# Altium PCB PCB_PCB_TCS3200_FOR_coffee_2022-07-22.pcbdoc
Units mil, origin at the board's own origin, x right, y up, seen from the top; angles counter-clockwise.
Board outline 2180 x 1812.92 mil, 2 copper layers (Top Layer, Bottom Layer); 51 components, 41 nets, 59 pads, 17 vias.
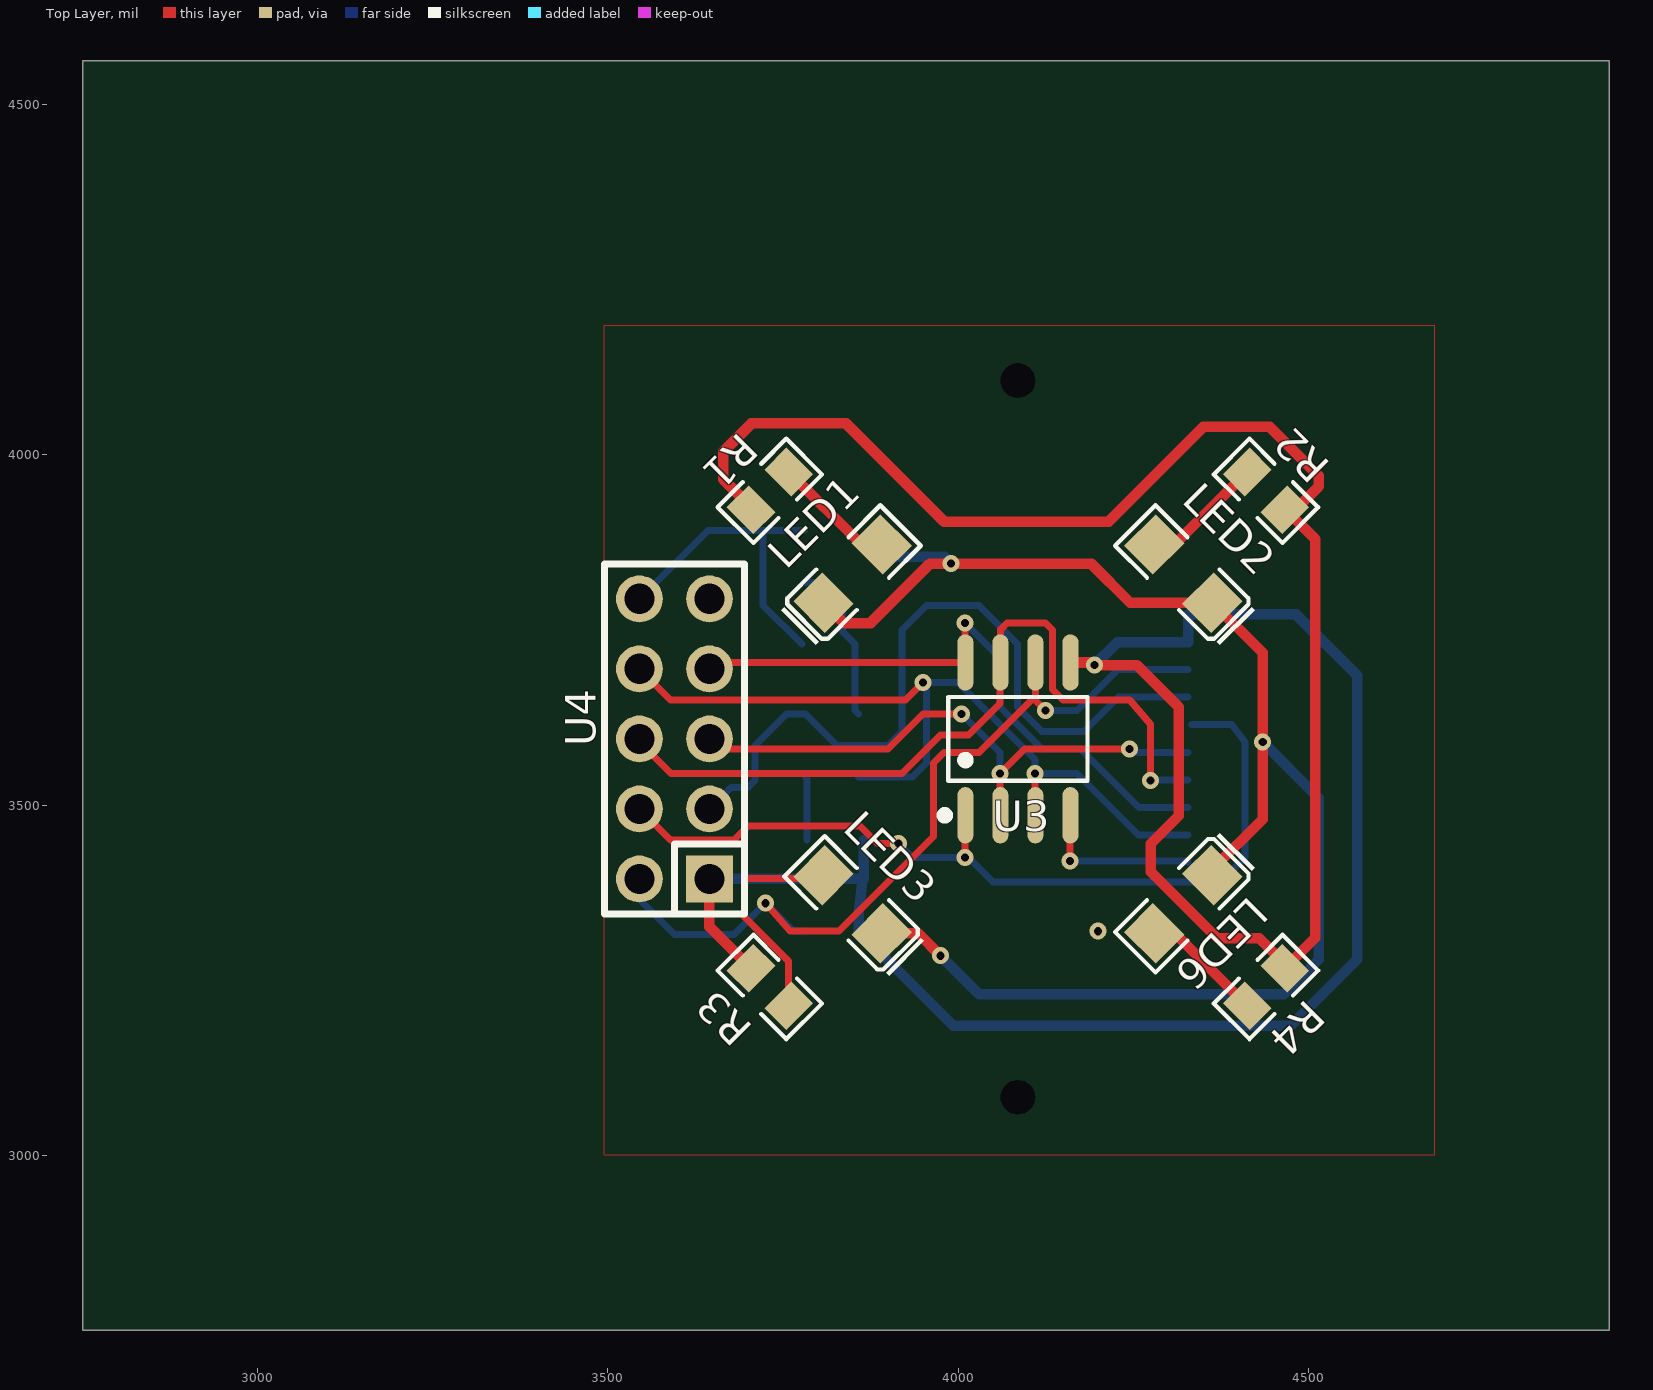
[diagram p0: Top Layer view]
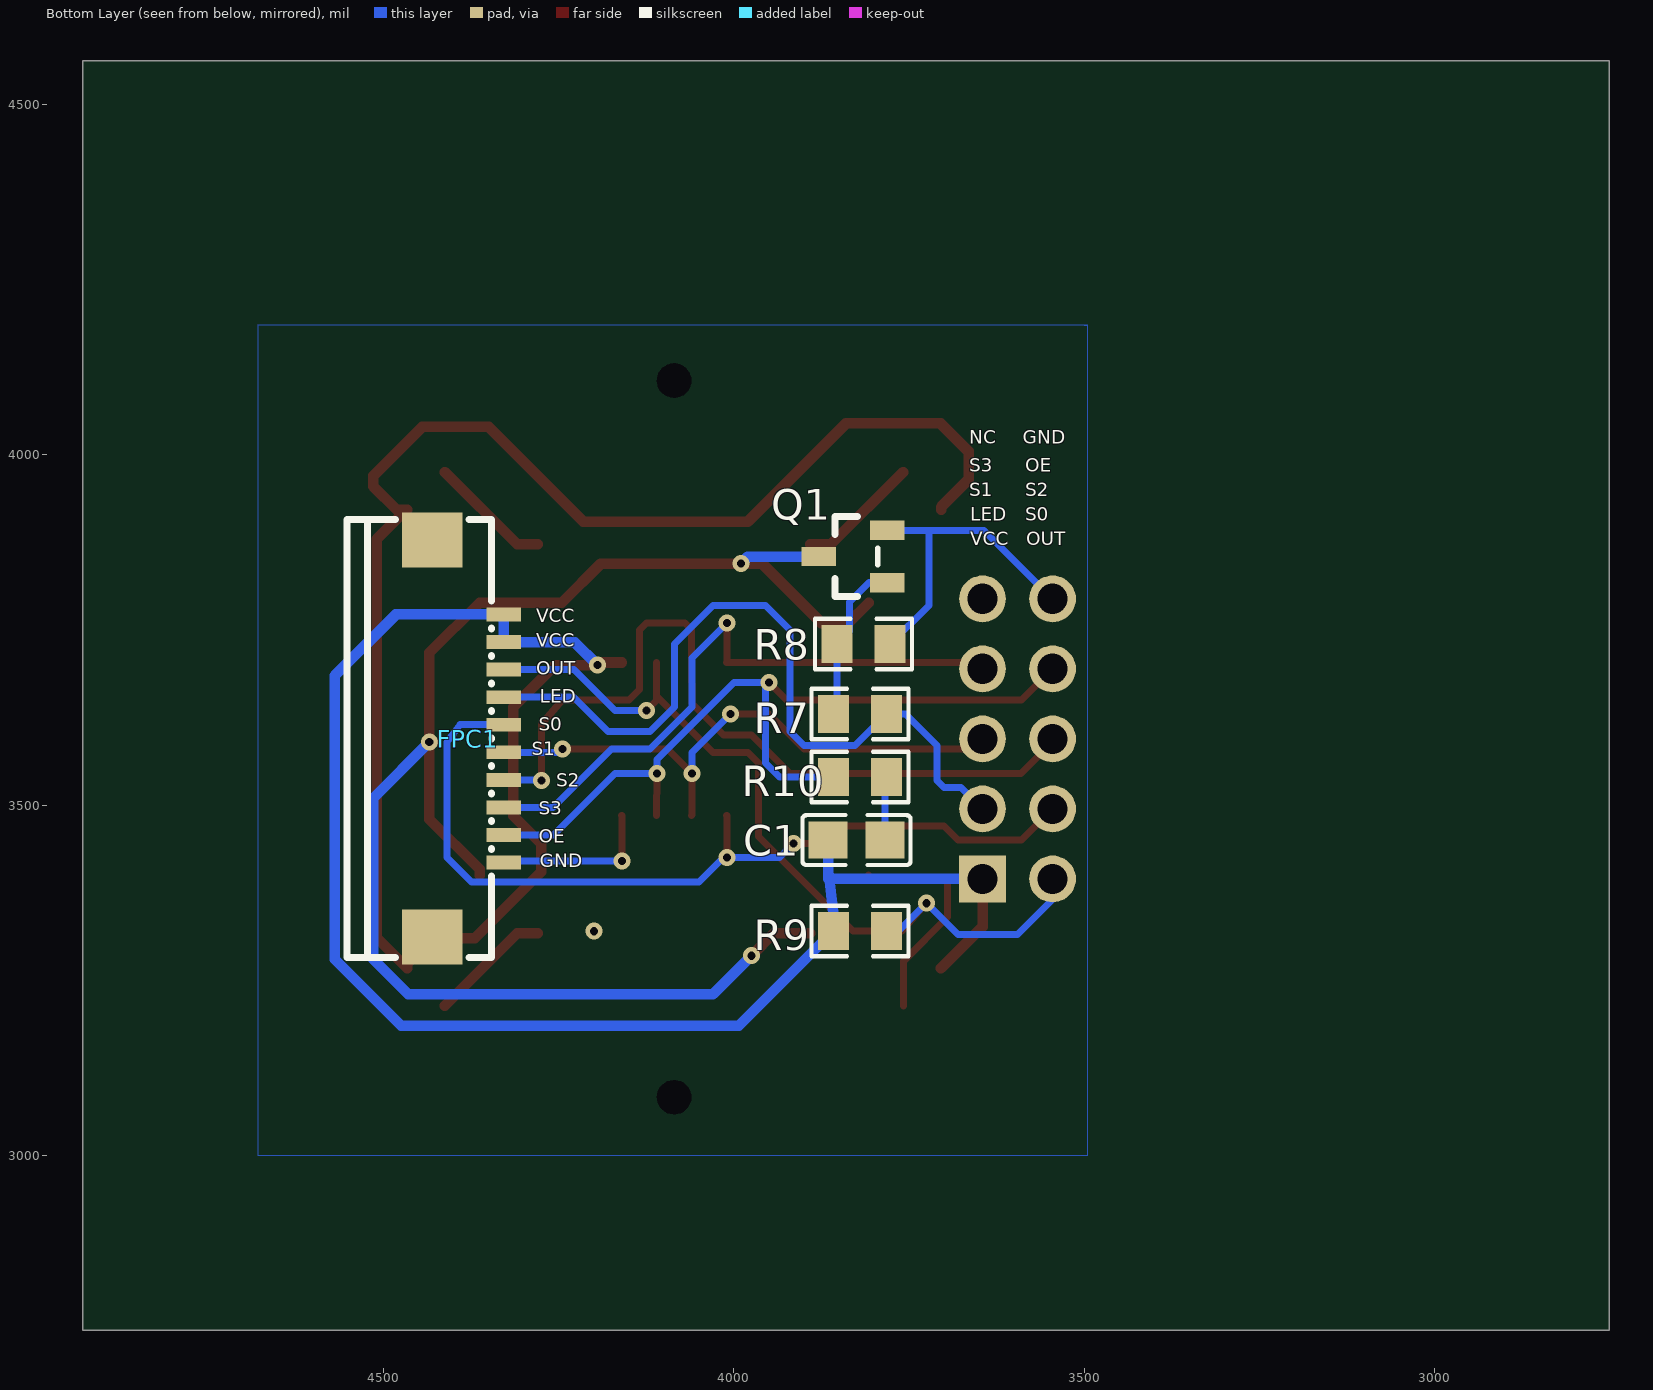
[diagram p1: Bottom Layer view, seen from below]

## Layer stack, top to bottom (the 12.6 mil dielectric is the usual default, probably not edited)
Top Solder: solder mask 0.4, Solder Resist, Dk 3.5
Top Layer: signal copper 1.4
Dielectric 1: dielectric 12.6, FR-4, Dk 4.8
Bottom Layer: signal copper 1.4
Bottom Solder: solder mask 0.4, Solder Resist, Dk 3.5

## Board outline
4930,2750 2750,2750 2750,4562.92 4930,4562.92
cut-out: 4110.16,4106.26 ccw(c4085.55,4106.26) 4060.94,4106.26 ccw(c4085.55,4106.26)
cut-out: 4110.16,3082.64 ccw(c4085.55,3082.64) 4060.94,3082.64 ccw(c4085.55,3082.64)

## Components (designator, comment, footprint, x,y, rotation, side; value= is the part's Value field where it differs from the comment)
C1 "0.1u" C0805 3825,3450 r0 bottom
FPC1 "AFA01-S10FCC-00" FPC-SMD_AFA01-S10FCC-00 4380,3595 r270 bottom
LED1 "HL-PC-3216H233W(6000-7000K)" LED1206-R-RD_WHITE 3849.33,3830.67 r45 top
LED2 "HL-PC-3216H233W(6000-7000K)" LED1206-R-RD_WHITE 4321.77,3830.67 r135 top
LED3 "HL-PC-3216H233W(6000-7000K)" LED1206-R-RD_WHITE 3849.33,3358.23 r135 top
LED6 "HL-PC-3216H233W(6000-7000K)" LED1206-R-RD_WHITE 4321.77,3358.23 r225 top
Q1 "8050(SOT-23)" SOT-23-3_L2.9-W1.3-P1.90-LS2.4-TR 3830,3855 r180 bottom
R1 "220" R0805 3731.22,3948.78 r45 top
R2 "220" R0805 4439.88,3948.78 r135 top
R3 "220" R0805 3731.22,3240.12 r315 top
R4 "220" R0805 4439.88,3240.12 r225 top
R7 "4.7K" R0805 3820,3630 r0 bottom
R8 "10K" R0805 3815,3730 r180 bottom
R9 "10K" R0805 3820,3320 r0 bottom
R10 "10K" R0805 3820,3540 r0 bottom
U3 "TCS3200D-TR" SOIC-8_L4.9-W3.9-P1.27-LS6.0-BL 4085.55,3594.45 r0 top
U4 "IDC10" HDR-TH_10P-P2.54-V-M-R2-C5-S2.54 3595,3594.45 r90 top
? "" ? 0,0 r0 top
? "" ? 0,0 r0 top
? "" ? 0,0 r0 top
? "" ? 0,0 r0 top
? "" ? 0,0 r0 top
? "" ? 0,0 r0 top
? "" ? 0,0 r0 top
? "" ? 0,0 r0 top
? "" ? 0,0 r0 top
? "" ? 0,0 r0 top
? "" ? 0,0 r0 top
? "" ? 0,0 r0 top
? "" ? 0,0 r0 top
? "" ? 0,0 r0 top
? "" ? 0,0 r0 top
? "" ? 0,0 r0 top
? "" ? 0,0 r0 top
? "" ? 0,0 r0 top
? "" ? 0,0 r0 top
? "" ? 0,0 r0 top
? "" ? 0,0 r0 top
? "" ? 0,0 r0 top
? "" ? 0,0 r0 top
? "" ? 0,0 r0 top
? "" ? 0,0 r0 top
? "" ? 0,0 r0 top
? "" ? 0,0 r0 top
? "" ? 0,0 r0 top
? "" ? 0,0 r0 top
? "" ? 0,0 r0 top
? "" ? 0,0 r0 top
? "" ? 0,0 r0 top
? "" ? 0,0 r0 top
? "" ? 0,0 r0 top

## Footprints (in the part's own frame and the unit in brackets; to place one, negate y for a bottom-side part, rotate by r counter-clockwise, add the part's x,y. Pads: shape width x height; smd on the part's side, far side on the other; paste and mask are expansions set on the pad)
C0805 [mm]
  rect 1.41x1.35 smd: 1(-1.03,0) 2(1.03,0)
  silkscreen extent -1.96,-0.9 1.96,0.9
FPC-SMD_AFA01-S10FCC-00 [mm]
  rect 0.5x1.25 smd: 1(-4.5,1.3) 2(-3.5,1.3) 3(-2.501,1.3) 4(-1.5,1.3) 5(-0.501,1.3) 6(0.499,1.3) 7(1.5,1.3) 8(2.499,1.3) 9(3.5,1.3) 10(4.499,1.3)
  rect 2x2.2 smd: 11(-7.2,-1.3) 12(7.2,-1.3)
  silkscreen extent -7.94,-4.39 7.95,0.86
HDR-TH_10P-P2.54-V-M-R2-C5-S2.54 [mm]
  rect 1.7x1.7 hole 1.1: 1(-5.08,-1.27)
  round 1.7 hole 1.1: 2(-5.08,1.27) 3(-2.54,-1.27) 4(-2.54,1.27) 5(0,-1.27) 6(0,1.27) 7(2.54,-1.27) 8(2.54,1.27) 9(5.08,-1.27) 10(5.08,1.27)
  silkscreen extent -6.35,-2.54 6.35,2.54
LED1206-R-RD_WHITE [mm]
  rect 1.485x1.62 smd: 1(1.493,0) 2(-1.493,0)
  silkscreen extent -2.77,-1.04 2.46,1.04
R0805 [mil]
  rect 44.59x54.21 smd: 1(-38.04,0) 2(38.04,0)
  silkscreen extent -69,-36 69,36
SOIC-8_L4.9-W3.9-P1.27-LS6.0-BL [mm]
  oval 0.588x2.045 smd: 1(-1.905,-2.772) 2(-0.635,-2.772) 3(0.635,-2.772) 4(1.905,-2.772) 5(1.905,2.772) 6(0.635,2.772) 7(-0.635,2.772) 8(-1.905,2.772)
  silkscreen extent -2.8,-2.92 2.53,1.52
SOT-23-3_L2.9-W1.3-P1.90-LS2.4-TR [mm]
  rect 1.25x0.7 smd: 1(1.25,0.95) 2(1.25,-0.95) 3(-1.25,0)
  silkscreen extent -0.65,-1.46 0.9,1.46
? [mil]

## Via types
v1: diameter 24, hole 12, Top Layer to Bottom Layer, 17 vias

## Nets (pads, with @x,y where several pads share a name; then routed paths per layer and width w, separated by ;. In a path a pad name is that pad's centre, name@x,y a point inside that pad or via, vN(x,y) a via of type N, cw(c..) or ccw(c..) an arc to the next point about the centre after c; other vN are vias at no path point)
5V: 
5V_IP5306_IN: 
$1N4498: 
$1N4499: 
$1N4601: 
$1N6976: 
$1N7176: 
$2N28: 
$2N29: 
$2N68: 
$2N124: 
$2N158: 
$2N300: 
$2N3097: 
BAT: 
D2: FPC1.2 R1.1 R2.1 R3.1 R4.1 U3.5 | length 4750.9
  Top Layer w15: 3645,3394.45 3645,3326.34 R3.1 ; R1.1 3704.3,3925.7 3665,3965 3665,4005 3705,4045 3840,4045 3980,3905 4215,3905 4350,4040 4445,4040 4515,3970 4515,3955 4481.9,3921.9 R2.1 4468.12,3921.88 4510,3880 4510,3310.24 R4.1 4466.78,3273.22 4430,3310 4370,3310 4275,3405 4275,3445 4315,3485 4315,3640 4255,3700 v1(4195,3700) 4191.4,3703.6 U3.5
  Bottom Layer w15: 3645,3394.45 3865,3395 3865.55,3450 ; 3858,3320 3993,3185 4475,3185 4570,3280 4570,3685 4482.8,3772.2 4328.8,3772.2 FPC1.2 4227.8,3732.8 v1(4195,3700) ; 3858.04,3320 3858.04,3346.41 3865,3405
GND: C1.1 FPC1.10 FPC1.11 FPC1.12 Q1.1 R10.1 U3.4 U4.10 | length 795
  Top Layer w10: v1(4160,3420) 4160,3484.75 U3.4@4160.55,3485.3
  Bottom Layer w10: U4.10 3642.95,3892.4 Q1.1 ; 3721.69,3892.4 3721.69,3785.27 3776.96,3730 ; R10.1 3784.45,3537.51 C1.1 ; v1@4155,3425 v1(4160,3420) 4326.66,3420 FPC1.10
  other v1: 4200,3320
I2C_SCL: 
I2C_SDA: 
LED_C: FPC1.4 R7.1 U4.3 | length 1103.3
  Bottom Layer w10: U4.3 3675.55,3525 3700,3525 3710,3535 3710,3585 3755,3630 R7.1 3826.96,3585 3900,3585 3920,3605 3920,3750 3955,3785 4030,3785 4085,3730 4085,3640 4120,3605 4180,3605 4229.06,3654.06 FPC1.4
LED_E: LED1.2 LED2.2 LED3.2 LED6.2 | length 2218.5
  Top Layer w15: LED1.2 3836.9,3760 3875,3760 3960,3845 v1(3990,3845) 4190,3845 4245.88,3789.12 LED2.2 4435,3717.44 v1(4435,3590) 4435,3480 4363.32,3408.32 LED6.2 ; LED3.2 3943.32,3316.68 v1(3975,3285)
  Bottom Layer w15: 3879.2,3855 3980,3855 v1(3990,3845) ; v1@3970,3285 v1(3975,3285) 4030,3230 4430,3230 4465,3230 4515,3280 4515,3510 v1(4435,3590)
OE: FPC1.9 U3.3 U4.8 | length 1201.5
  Top Layer w10: U4.8 3589.45,3650 3925,3650 v1(3950,3675) v1@3955,3675 ; v1(4110,3545) U3.3@4110.5,3485.3
  Bottom Layer w10: 3858.04,3540 3935,3540 3955,3560 3955,3670 v1(3950,3675) 4000,3675 4110,3565 v1(4110,3545) 4170,3545 4257.8,3457.2 FPC1.9
OUT: FPC1.3 R9.1 U3.6 U4.2 | length 1277.2
  Top Layer w10: v1(3725,3360) 3760,3320 3830,3320 3965,3455 3965,3560 3980,3575 4030,3575 4110.5,3655.5 U3.6@4110.5,3703.6 ; U3.6 4110.55,3649.45 v1(4125,3635)
  Bottom Layer w10: U4.2@3545,3394.45 3545,3365 3595,3315 3680,3315 v1(3725,3360) 3765,3320 R9.1 ; v1(4125,3635) 4170,3635 4228.45,3693.45 FPC1.3
Q1_2: Q1.2 R8.1 | length 235.2
  Bottom Layer w10: Q1.2 3807.4,3817.6 3835,3790 3835,3748.04 R8.1 3853.04,3635 3858.04,3630
R1_2:  | length 175.6
  Top Layer w15: 3758.12,3975.68 3861.58,3872.22 3890.88,3872.22
R2_2:  | length 175.6
  Top Layer w15: 4280.22,3872.22 4309.52,3872.22 4412.98,3975.68
R3_2:  | length 322.7
  Top Layer w10: 3758.12,3213.22 3758.12,3276.88 3695,3340 3695,3395 3803,3395 3807.78,3399.78
R4_2:  | length 175.6
  Top Layer w15: 4280.22,3316.68 4309.52,3316.68 4412.98,3213.22
RST: 
RXD: 
S0: FPC1.5 U4.4 | length 1248.5
  Top Layer w10: U4.4 3589.45,3450 3680,3450 3700,3470 3860,3470 3885,3445 v1(3915,3445) ; v1(4010,3425) 4010,3484.8 4010.5,3485.3
  Bottom Layer w10: v1(3915,3445) 3935,3425 v1(4010,3425) ; v1@4015,3425 4050,3390 4375,3390 4410,3425 4410,3590 4391.1,3615 FPC1.5@4333.8,3615
S1: FPC1.6 U3.2 U4.5 | length 839.6
  Top Layer w10: U4.5 3659.45,3580 3900,3580 3950,3630 v1(4005,3630) ; U3.2@4060.55,3485.3 4060,3485.85 v1(4060,3545) 4095,3580 v1(4245,3580)
  Bottom Layer w10: v1(4005,3630) 4060,3575 v1(4060,3545) ; v1(4245,3580) 4249.65,3575.35 FPC1.6
S2: FPC1.7 U3.7 U4.6 | length 1148.5
  Top Layer w10: U4.6@3545,3594.5 3545,3590 3590,3545 3920,3545 3975,3600 4015,3600 4060,3645 U3.7@4060.5,3703.6 ; U3.7@4061,3704 4061,3751 4070,3760 4125,3760 4135,3750 4135,3665 4150,3650 4245,3650 4275,3615 4275,3575 v1(4275,3535)
  Bottom Layer w10: v1(4275,3535) 4275.95,3535.95 FPC1.7
S3: FPC1.8 U3.8 U4.7 | length 894.9
  Top Layer w10: U4.7 3654.15,3703.6 U3.8 4010,3704.15 v1(4010,3760)
  Bottom Layer w10: v1(4010,3760) 4060,3710 4060,3640 4120,3580 4175,3580 4258.4,3496.6 FPC1.8
SWC: 
SWD: 
TXD: 
U4_9: U4.9
USB_DN: 
USB_DP: 
"": 
pads on no net: C1.2 FPC1.1 LED1.1 LED2.1 LED3.1 LED6.1 Q1.3 R1.2 R2.2 R3.2 R4.2 R7.2 R8.2 R9.2 R10.2 U3.1 U4.1

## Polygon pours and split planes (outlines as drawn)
GND on Bottom Layer (solid, remove dead copper): 3495,4185 4680,4185 4680,3000 3495,3000 3495,4185 3500,4185
GND on Top Layer (solid, remove dead copper, pour order 1): 3495,4185 4680,4185 4680,3000 3495,3000

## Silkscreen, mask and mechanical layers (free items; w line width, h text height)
Bottom Overlay:
  text "GND" at 3587.24,4016.08 h19.14
  text "NC" at 3663.69,4016.08 h19.14
  text "OE" at 3583.69,3976.08 h19.14
  text "S3" at 3663.69,3976.08 h19.14
  text "S2" at 3583.69,3941.08 h19.14
  text "S1" at 3663.69,3941.08 h19.14
  text "S0" at 3583.69,3906.08 h19.14
  text "LED" at 3662.24,3906.08 h19.14
  text "OUT" at 3582.24,3871.08 h19.14
  text "VCC" at 3662.24,3871.08 h19.14
  text "VCC" at 4282.24,3761.08 h19.14
  text "VCC" at 4282.24,3726.08 h19.14
  text "OUT" at 4282.24,3686.08 h19.14
  text "LED" at 4277.24,3646.08 h19.14
  text "S0" at 4278.69,3606.08 h19.14
  text "S1" at 4288.69,3571.08 h19.14
  text "S2" at 4253.69,3526.08 h19.14
  text "S3" at 4278.69,3486.08 h19.14
  text "OE" at 4278.69,3446.08 h19.14
  text "GND" at 4277.24,3411.08 h19.14
Mechanical 1:
  circle w1: c4085.55,4106.26 r24.61
  circle w1: c4085.55,3082.64 r24.61
  lines w10: 3495,3082.64 ccw(c3573.74,3082.64) 3573.74,3003.9 4597.36,3003.9 ccw(c4597.36,3082.64) 4676.1,3082.64 4676.1,4106.26 ccw(c4597.36,4106.26) 4597.36,4185 3573.74,4185 ccw(c3573.74,4106.26) 3495,4106.26 3495,3082.64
